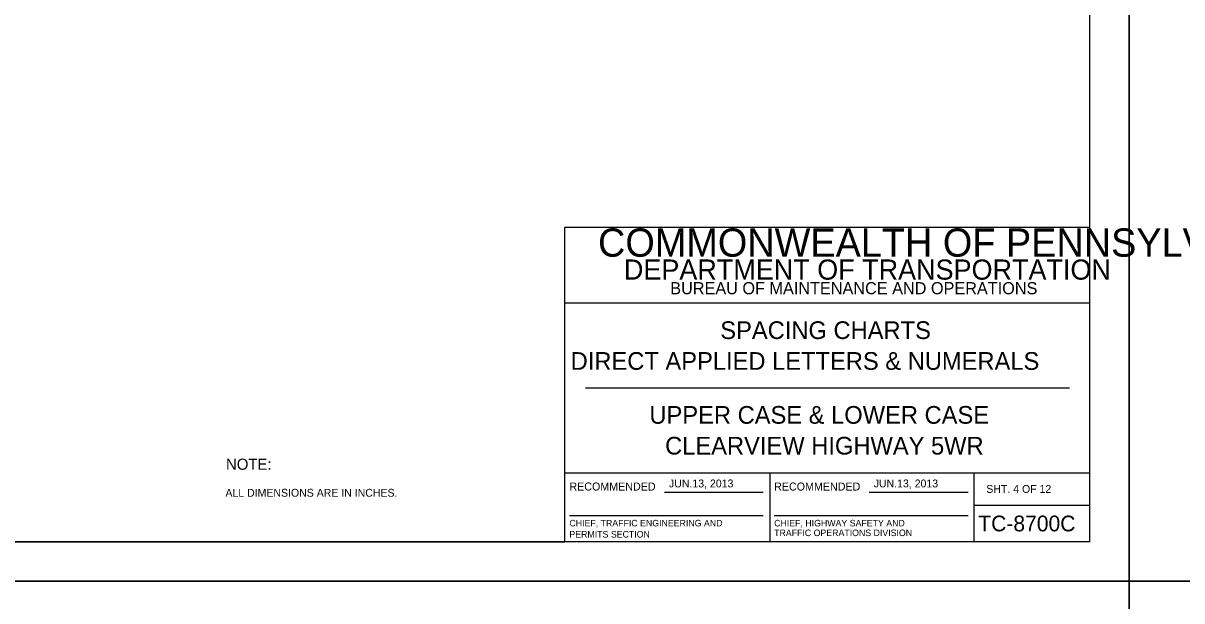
# Model space of a CAD drawing. Extents: x 638421 to 641849, y 297270 to 299646.
# Drawn here: x 639681.9 to 640123.3, y 298450.1 to 298670.4 of the extents above; entities that cross this region are included whole.
import ezdxf

# ---------------------------------------------------------------- set-up
doc = ezdxf.new("R2010")
doc.units = 0
for name, color, linetype in [('1', 7, 'Continuous'), ('2', 7, 'Continuous'), ('XCS-GRID-HVGL', 7, 'Continuous')]:
    doc.layers.add(name, color=color, linetype=linetype)

msp = doc.modelspace()

# ---------------------------------------------------------------- linework, layer by layer
at = {"layer": '1'}
for p, q in [((640088.31, 298472.63), (640088.31, 299036.63)), ((639888.31, 298472.63), (639888.31, 298592.63)), ((639888.31, 298592.63), (640088.31, 298592.63)), ((640088.31, 298563.63), (639888.31, 298563.63)), ((639896.06, 298531.31), (640080.56, 298531.31)), ((639888.31, 298499), (640088.31, 298499)), ((639966.31, 298499), (639966.31, 298472.63)), ((640044.19, 298472.63), (640044.19, 298499)), ((639926.24, 298491.57), (639963.87, 298491.57)), ((640004.24, 298491.57), (640041.87, 298491.57)), ((640044.19, 298486.63), (640088.31, 298486.63)), ((639889.99, 298482.68), (639963.87, 298482.68)), ((639967.99, 298482.68), (640041.87, 298482.68)), ((640088.31, 298472.63), (639302.31, 298472.63)), ((639302.31, 298472.63), (639888.31, 298472.63))]:
    msp.add_line(p, q, dxfattribs=at)
at = {"layer": 'XCS-GRID-HVGL'}
for points in [[(639262.31, 299051.63), (640103.31, 299051.63), (640103.31, 298457.63), (639262.31, 298457.63)], [(640103.31, 299051.63), (640944.31, 299051.63), (640944.31, 298457.63), (640103.31, 298457.63)], [(639262.31, 298457.63), (640103.31, 298457.63), (640103.31, 297863.63), (639262.31, 297863.63)], [(640103.31, 298457.63), (640944.31, 298457.63), (640944.31, 297863.63), (640103.31, 297863.63)]]:
    msp.add_lwpolyline(points, close=True, dxfattribs=at)

# ---------------------------------------------------------------- texts
at = {"layer": '1'}
for s, height, p in [('COMMONWEALTH OF PENNSYLVANIA', 10.7828, (639900.9, 298581.36)), ('DEPARTMENT OF TRANSPORTATION', 7.6837, (639910.76, 298572.61)), ('BUREAU OF MAINTENANCE AND OPERATIONS', 4.6253, (639928.41, 298567.04)), ('SPACING CHARTS', 6.75, (639947.47, 298549.97)), ('DIRECT APPLIED LETTERS & NUMERALS', 6.75, (639890.47, 298538.22)), ('UPPER CASE & LOWER CASE', 6.75, (639920.47, 298517.66)), ('CLEARVIEW HIGHWAY 5WR', 6.75, (639926.45, 298505.91)), ('RECOMMENDED', 3.048, (639889.99, 298492.2)), ('RECOMMENDED', 3.048, (639967.99, 298492.2)), ('SHT. 4 OF 12', 3, (640048.82, 298491.31)), ('CHIEF, TRAFFIC ENGINEERING AND', 2.5, (639889.99, 298478.51)), ('CHIEF, HIGHWAY SAFETY AND', 2.5, (639967.99, 298478.51)), ('TC-8700C', 6, (640045.77, 298476.63)), ('PERMITS SECTION', 2.5, (639889.99, 298474.26)), ('TRAFFIC OPERATIONS DIVISION', 2.5, (639967.99, 298474.81))]:
    msp.add_text(s, height=height, dxfattribs=at).set_placement(p)
at = {"layer": '2'}
for s, height, p in [('NOTE:', 4.25, (639759.16, 298500.1)), ('ALL DIMENSIONS ARE IN INCHES.', 3, (639758.94, 298489.83)), ('JUN.13, 2013', 3, (639927.93, 298493.39)), ('JUN.13, 2013', 3, (640005.93, 298493.39))]:
    msp.add_text(s, height=height, dxfattribs=at).set_placement(p)

doc.saveas('drawing.dxf')
